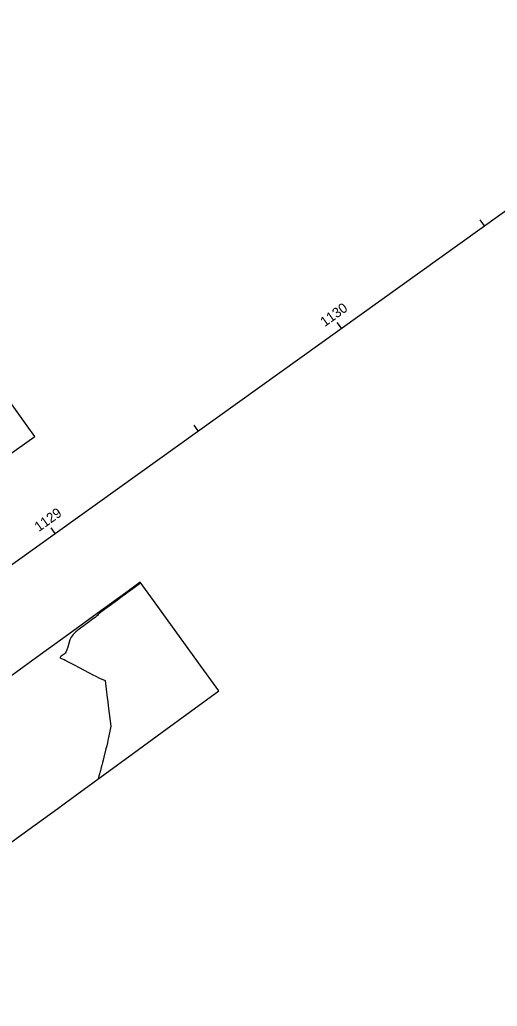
# Model space of a CAD drawing. Extents: x 2079879 to 2092887, y 778083 to 784051.
# Drawn here: x 2084709.2 to 2084844.9, y 781386.8 to 781666.9 of the extents above; entities that cross this region are included whole.
import ezdxf

# ---------------------------------------------------------------- set-up
doc = ezdxf.new("R2010")
doc.units = 0
for name, color, linetype in [('DT_X_Contour_Minor', 7, 'Continuous'), ('DT_X_TIN_Hull', 7, 'Continuous'), ('GE_X_CL_20', 7, 'Continuous')]:
    doc.layers.add(name, color=color, linetype=linetype)

msp = doc.modelspace()

# ---------------------------------------------------------------- linework, layer by layer
at = {"layer": 'DT_X_Contour_Minor'}
msp.add_lwpolyline([(2084743.64, 781507.02), (2084740.91, 781505.03), (2084740.39, 781504.66), (2084739.99, 781504.37), (2084739.73, 781504.18), (2084739.59, 781504.08), (2084739.39, 781503.93), (2084739.18, 781503.78), (2084738.71, 781503.44), (2084737.97, 781502.9), (2084736.96, 781502.17), (2084733.93, 781499.96), (2084732.92, 781499.22), (2084732.18, 781498.67), (2084731.7, 781498.29), (2084731.49, 781498.09), (2084731.27, 781497.81), (2084731.06, 781497.62), (2084730.6, 781497.26), (2084729.9, 781496.73), (2084728.95, 781496.03), (2084726.07, 781493.94), (2084725.1, 781493.16), (2084724.34, 781492.38), (2084723.79, 781491.6), (2084723.46, 781490.83), (2084722.85, 781488.78), (2084722.61, 781488.08), (2084722.36, 781487.52), (2084722.09, 781487.09), (2084721.8, 781486.81), (2084721, 781486.23), (2084720.77, 781486.03), (2084720.66, 781485.87), (2084720.68, 781485.73), (2084720.82, 781485.64), (2084721.79, 781485.26), (2084722.08, 781485.1), (2084722.16, 781485.06), (2084722.27, 781485), (2084722.43, 781484.92), (2084722.62, 781484.82), (2084723.17, 781484.55), (2084723.5, 781484.38), (2084724.06, 781484.09), (2084724.85, 781483.67), (2084725.87, 781483.12), (2084728.92, 781481.51), (2084729.96, 781480.96), (2084730.8, 781480.52), (2084731.45, 781480.2), (2084731.89, 781480), (2084733.49, 781479.31), (2084733.87, 781476.04), (2084733.96, 781475.28), (2084734.07, 781474.37), (2084734.19, 781473.34), (2084734.34, 781472.17), (2084735.05, 781466.38), (2084734.43, 781463.11), (2084734.28, 781462.39), (2084734.11, 781461.61), (2084733.92, 781460.8), (2084733.7, 781459.93), (2084733.1, 781457.56), (2084732.89, 781456.73), (2084732.72, 781456.05), (2084732.58, 781455.49), (2084732.47, 781455.07), (2084732.24, 781454.13), (2084732.15, 781453.78), (2084732.06, 781453.45), (2084731.98, 781453.13), (2084731.9, 781452.82), (2084731.53, 781451.43)], dxfattribs=at)
at = {"layer": 'DT_X_TIN_Hull'}
for points in [[(2084705.36, 781542.84), (2084713.49, 781548.65), (2084711.32, 781551.66), (2084704.65, 781560.88)], [(2084703.82, 781431.24), (2084711.91, 781437.13), (2084719.99, 781443.02), (2084725.4, 781446.96), (2084733.48, 781452.85), (2084741.55, 781458.74), (2084749.63, 781464.64), (2084757.71, 781470.54), (2084765.78, 781476.44), (2084760.03, 781484.38), (2084753.41, 781493.52), (2084746.47, 781503.11), (2084743.45, 781507.28), (2084739.3, 781504.26), (2084731.21, 781498.37), (2084723.12, 781492.49), (2084715.03, 781486.62), (2084706.93, 781480.74)]]:
    msp.add_lwpolyline(points, dxfattribs=at)
at = {"layer": 'GE_X_CL_20'}
for p, q in [((2079923.52, 778084.44), (2085691.45, 782217.74)), ((2084841.22, 781608.46), (2084840.05, 781610.08)), ((2084800.58, 781579.33), (2084799.41, 781580.96)), ((2084759.93, 781550.21), (2084758.77, 781551.84)), ((2084719.29, 781521.09), (2084718.13, 781522.71))]:
    msp.add_line(p, q, dxfattribs=at)

# ---------------------------------------------------------------- texts
for s, p in [('1130', (2084795.85, 781579.64)), ('1129', (2084714.64, 781521.45))]:
    msp.add_text(s, height=2.8, rotation=35.6254, dxfattribs=at).set_placement(p)

doc.saveas('drawing.dxf')
